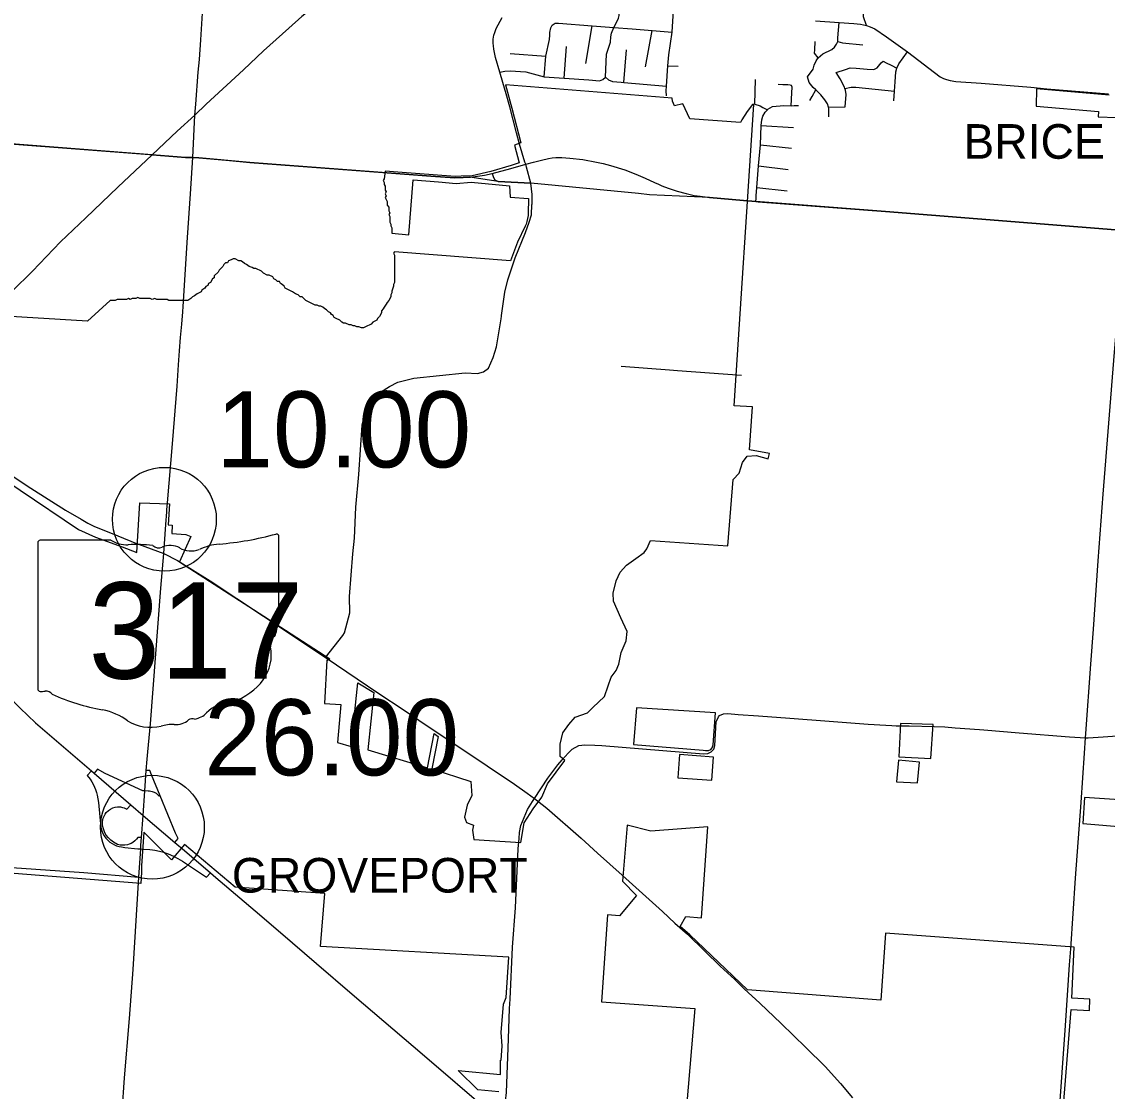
# Model space of a CAD drawing. Extents: x 1659811 to 1934326, y 644115 to 934867.
# Drawn here: x 1859259 to 1874937, y 684419 to 699875 of the extents above; entities that cross this region are included whole.
import ezdxf

# ---------------------------------------------------------------- set-up
doc = ezdxf.new("R2010")
doc.units = 0
for name, color, linetype in [('Default', 7, 'Continuous'), ('GM_X_City_Street', 7, 'Continuous'), ('GM_X_Corporation', 7, 'Continuous'), ('GM_X_Corporation_Text', 7, 'Continuous'), ('GM_X_County_Road', 7, 'Continuous'), ('GM_X_Interchange_Ramps', 7, 'Continuous'), ('GM_X_Interstate_Route', 7, 'Continuous'), ('GM_X_State_Route', 7, 'Continuous'), ('GM_X_State_Shield', 7, 'Continuous'), ('GM_X_Township', 7, 'Continuous'), ('GM_X_Township_Road', 7, 'Continuous'), ('GM_X_US_Route', 7, 'Continuous')]:
    doc.layers.add(name, color=color, linetype=linetype)

msp = doc.modelspace()

# ---------------------------------------------------------------- linework, layer by layer
at = {"layer": 'Default'}
for centre in [(1861320, 692685), (1861146, 688236)]:
    msp.add_circle(centre, 750, dxfattribs=at)
at = {"layer": 'GM_X_City_Street'}
for points in [[(1867689, 699074), (1867705, 699405), (1867764, 699580), (1867769, 699656), (1867777, 699710), (1867811, 699792), (1867859, 699882), (1867878, 699928), (1867890, 699967), (1867902, 700098), (1867921, 700440), (1867930, 700572), (1867936, 700755), (1867950, 700831), (1867977, 700904), (1867994, 700938), (1868035, 701005)], [(1871460, 699819), (1871415, 699946), (1871415, 700030), (1871420, 700173), (1871424, 700234)], [(1868572, 698806), (1868565, 698876), (1868570, 698945), (1868593, 699236), (1868606, 699398), (1868653, 699725), (1868674, 700037)], [(1866244, 698866), (1866239, 698881), (1866165, 699146), (1866104, 699357), (1866088, 699432), (1866078, 699480), (1866071, 699526), (1866067, 699566), (1866070, 699624), (1866080, 699680), (1866091, 699717), (1866100, 699747), (1866111, 699776), (1866198, 699935)], [(1870917, 698502), (1870917, 698622), (1870912, 698639), (1870897, 698688), (1870860, 698747), (1870799, 698819), (1870727, 698889), (1870690, 698925), (1870633, 698996), (1870607, 699079), (1870690, 699188), (1870705, 699246), (1870731, 699310), (1870762, 699355), (1870830, 699409), (1870960, 699473), (1871000, 699505), (1871028, 699550), (1871046, 699590), (1871048, 699643), (1871065, 699862)], [(1870722, 699888), (1871065, 699862), (1871277, 699848), (1871371, 699838), (1871460, 699819), (1871514, 699800), (1871580, 699770), (1871747, 699655), (1872052, 699438), (1872525, 699078), (1872570, 699053), (1872613, 699038), (1872668, 699024), (1872748, 699013), (1873117, 698986), (1873833, 698927), (1874063, 698907)], [(1866807, 699079), (1866829, 699375), (1866881, 699616), (1866885, 699683), (1866888, 699719), (1866899, 699787), (1866922, 699827)], [(1866922, 699827), (1866964, 699853), (1867010, 699856), (1867496, 699815), (1867561, 699811), (1867811, 699792), (1868074, 699771), (1868363, 699747), (1868653, 699725)], [(1867407, 699273), (1867496, 699815)], [(1868267, 699221), (1868363, 699747)], [(1870762, 699355), (1870711, 699419), (1870712, 699467), (1870719, 699588)], [(1871046, 699590), (1871114, 699571), (1871407, 699543)], [(1866312, 699417), (1866829, 699375)], [(1867092, 699059), (1867127, 699515)], [(1867957, 698996), (1867992, 699471)], [(1871853, 698732), (1871863, 698871), (1871873, 699006), (1871885, 699149), (1871899, 699206), (1871927, 699266), (1872052, 699438)], [(1868593, 699236), (1868740, 699231)], [(1871020, 699143), (1871158, 699184), (1871223, 699208), (1871311, 699203), (1871468, 699190), (1871564, 699185), (1871614, 699209), (1871672, 699281), (1871699, 699307), (1871745, 699283), (1871815, 699246), (1871899, 699206)], [(1866165, 699146), (1866236, 699163), (1866313, 699167), (1866542, 699151), (1866807, 699079), (1867092, 699059), (1867450, 699033), (1867606, 699022), (1867650, 699039), (1867689, 699074)], [(1871153, 698643), (1871165, 698825), (1871156, 698886), (1871148, 698910), (1871141, 698928), (1871078, 699051), (1871020, 699143)], [(1867689, 699074), (1867734, 699033), (1867793, 699010), (1867919, 699000), (1867957, 698996), (1868570, 698945)], [(1869845, 698682), (1869856, 699040)], [(1870371, 698662), (1870381, 698847), (1870385, 698931), (1870375, 698954), (1870357, 698960), (1870325, 698961), (1870253, 698962), (1870184, 698967)], [(1871148, 698910), (1871237, 698928), (1871307, 698927), (1871863, 698871)], [(1866550, 697772), (1866538, 697818), (1866524, 697845), (1866448, 698105), (1866404, 698269), (1866307, 698645), (1866244, 698866)], [(1870639, 698739), (1870674, 698795), (1870727, 698889)], [(1874063, 698907), (1874957, 698831)], [(1869845, 698682), (1869926, 698658), (1869965, 698637), (1870031, 698601)], [(1870031, 698601), (1870037, 698610), (1870102, 698650), (1870267, 698663), (1870371, 698662), (1870414, 698663), (1870480, 698666)], [(1870912, 698639), (1871153, 698643)], [(1869861, 697276), (1869864, 697323), (1869867, 697360), (1869878, 697481), (1869902, 697791), (1869931, 698097), (1869938, 698375), (1869948, 698457), (1869963, 698511), (1869998, 698568), (1870031, 698601)], [(1869938, 698375), (1870407, 698346)], [(1859028, 698117), (1861107, 697956)], [(1869931, 698097), (1870375, 698046)], [(1861107, 697956), (1861145, 697954), (1861625, 697914), (1861731, 697912)], [(1861731, 697912), (1861818, 697909), (1862259, 697869)], [(1862259, 697869), (1862555, 697842), (1864476, 697696)], [(1869902, 697791), (1870329, 697740)], [(1869878, 697481), (1870316, 697430)], [(1869895, 697274), (1871736, 697131), (1875175, 696856)], [(1874409, 686478), (1874480, 687499), (1874558, 688592), (1874608, 689305), (1874622, 689526), (1874627, 689590), (1874698, 690594), (1874737, 691097), (1874807, 692083), (1874880, 693048), (1875039, 695102), (1875078, 695560), (1875115, 696086), (1875158, 696658), (1875175, 696856)], [(1860916, 692337), (1860948, 692324), (1861312, 692190), (1861508, 692091), (1861979, 691797), (1862752, 691283), (1863647, 690689), (1863658, 690682)], [(1867063, 689207), (1867152, 689304), (1867211, 689363), (1867304, 689414), (1867394, 689426), (1867534, 689423), (1867637, 689418), (1869107, 689295), (1869168, 689300), (1869217, 689324), (1869253, 689365), (1869269, 689417), (1869291, 689760), (1869321, 689831), (1869337, 689848), (1869394, 689874), (1869457, 689877), (1869607, 689866), (1869898, 689844), (1870354, 689811), (1870919, 689768), (1871486, 689726), (1871740, 689708), (1871825, 689704), (1871887, 689701), (1871962, 689700)], [(1872437, 689689), (1872589, 689685), (1872741, 689673), (1873090, 689646), (1873156, 689641), (1873664, 689601), (1874391, 689543), (1874622, 689526), (1874647, 689526)], [(1874647, 689526), (1874663, 689526), (1874879, 689540), (1875079, 689554), (1875308, 689585), (1875466, 689617), (1875725, 689669), (1875775, 689677), (1875996, 689696), (1876147, 689675), (1876610, 689595), (1876828, 689561), (1877210, 689494), (1877360, 689471)], [(1866709, 688615), (1866844, 688509), (1867338, 688077), (1867575, 687860), (1867931, 687545), (1867936, 687540)], [(1866306, 685614), (1866312, 685751), (1866346, 686500), (1866391, 687069), (1866430, 687924), (1866442, 688073)], [(1858280, 687713), (1860155, 687580), (1860950, 687512)], [(1866232, 684150), (1866259, 684403), (1866289, 685179), (1866306, 685614)]]:
    msp.add_lwpolyline(points, dxfattribs=at)
at = {"layer": 'GM_X_Corporation'}
for points in [[(1857547, 694243), (1860080, 692538), (1860327, 692427), (1860710, 692289), (1860920, 692207), (1860963, 692923), (1861392, 692910), (1861373, 692607), (1861434, 692602), (1861427, 692478), (1861632, 692467), (1861702, 692436), (1861540, 692070), (1862757, 691285), (1863709, 690671), (1863676, 690644), (1863665, 690650), (1863632, 690025), (1863867, 690010), (1863822, 689460), (1864017, 689402), (1864114, 690321), (1864344, 690182), (1864258, 689355), (1865121, 689095), (1865214, 689588), (1865272, 689548), (1865183, 689079), (1865744, 688897), (1865760, 688694), (1865692, 688556), (1865656, 688381), (1865683, 688304), (1865782, 688264), (1865771, 688194), (1865790, 688059), (1866466, 688014), (1866514, 688300), (1866645, 688503), (1866769, 688671), (1866852, 688861), (1867103, 689199), (1867038, 689259), (1867038, 689436), (1867076, 689597), (1867160, 689719), (1867254, 689824), (1867432, 689887), (1867506, 689964), (1867676, 690125), (1867728, 690280), (1867771, 690404), (1867843, 690501), (1867883, 690594), (1867915, 690759), (1867991, 690927), (1868002, 691062), (1867911, 691263), (1867807, 691503), (1867799, 691618), (1867843, 691794), (1867903, 691921), (1867995, 692022), (1868130, 692119), (1868250, 692205), (1868289, 692258), (1868340, 692380), (1869458, 692303), (1869536, 693259), (1869622, 693353), (1869670, 693504), (1869736, 693599), (1869866, 693609), (1870041, 693559), (1870059, 693637), (1869771, 693687), (1869812, 694308), (1869550, 694325), (1869833, 698679), (1869814, 698680), (1869737, 698577), (1869660, 698456), (1869641, 698418), (1868907, 698473), (1868806, 698690), (1868687, 698662), (1868657, 698726), (1868651, 698772), (1866245, 698962), (1866336, 698628), (1866470, 698123), (1866374, 698093), (1866443, 697834), (1866328, 697798), (1866034, 697709), (1865767, 697650), (1865608, 697641), (1865518, 697637), (1864693, 697702), (1864510, 697716), (1864495, 697606), (1864481, 697579), (1864495, 697551), (1864495, 697524), (1864508, 697497), (1864508, 697469), (1864508, 697442), (1864522, 697415), (1864508, 697388), (1864522, 697360), (1864508, 697333), (1864536, 697279), (1864536, 697224), (1864563, 697197), (1864563, 697142), (1864576, 697115), (1864563, 697088), (1864576, 697060), (1864576, 696979), (1864590, 696951), (1864590, 696924), (1864604, 696897), (1864604, 696818), (1864851, 696794), (1864914, 697591), (1865278, 697562), (1865532, 697538), (1865750, 697559), (1866305, 697505), (1866315, 697341), (1866579, 697320), (1866574, 697105), (1866572, 697073), (1866566, 697034), (1866555, 696987), (1866543, 696952), (1866530, 696922), (1866419, 696689), (1866317, 696418), (1864641, 696550), (1864631, 696529), (1864645, 696501), (1864645, 696229), (1864645, 696106), (1864631, 696079), (1864631, 696052), (1864617, 696024), (1864604, 695983), (1864604, 695956), (1864590, 695929), (1864590, 695902), (1864563, 695847), (1864536, 695820), (1864522, 695793), (1864495, 695752), (1864481, 695724), (1864454, 695697), (1864454, 695670), (1864426, 695615), (1864399, 695588), (1864386, 695561), (1864331, 695533), (1864304, 695506), (1864222, 695465), (1864195, 695452), (1864167, 695452), (1864127, 695465), (1864099, 695465), (1864072, 695479), (1864045, 695479), (1864017, 695493), (1863990, 695493), (1863936, 695520), (1863908, 695520), (1863881, 695533), (1863854, 695561), (1863799, 695588), (1863772, 695602), (1863758, 695629), (1863731, 695643), (1863718, 695670), (1863690, 695683), (1863663, 695711), (1863636, 695724), (1863608, 695752), (1863581, 695765), (1863554, 695765), (1863527, 695779), (1863499, 695779), (1863390, 695833), (1863363, 695847), (1863309, 695902), (1863281, 695902), (1863254, 695929), (1863213, 695942), (1863172, 695970), (1863063, 696024), (1863049, 696052), (1863022, 696079), (1862995, 696092), (1862981, 696120), (1862954, 696120), (1862927, 696147), (1862899, 696161), (1862886, 696188), (1862831, 696215), (1862804, 696215), (1862750, 696242), (1862722, 696270), (1862640, 696311), (1862613, 696311), (1862586, 696324), (1862545, 696338), (1862504, 696365), (1862477, 696379), (1862450, 696406), (1862422, 696420), (1862395, 696420), (1862341, 696447), (1862313, 696447), (1862286, 696433), (1862245, 696420), (1862231, 696392), (1862204, 696392), (1862177, 696365), (1862163, 696338), (1862109, 696283), (1862095, 696256), (1862041, 696201), (1862041, 696174), (1862013, 696161), (1861986, 696106), (1861959, 696092), (1861945, 696065), (1861918, 696051), (1861904, 696024), (1861863, 695997), (1861850, 695970), (1861795, 695942), (1861754, 695915), (1861727, 695902), (1861700, 695874), (1861659, 695847), (1861427, 695847), (1861386, 695847), (1861359, 695861), (1861209, 695861), (1861182, 695874), (1861141, 695861), (1861113, 695874), (1860964, 695874), (1860936, 695888), (1860909, 695874), (1860854, 695874), (1860827, 695861), (1860800, 695874), (1860773, 695861), (1860636, 695861), (1860609, 695847), (1860536, 695847), (1860208, 695548), (1858861, 695628)], [(1874965, 698815), (1873913, 698904), (1873911, 698654), (1874808, 698580), (1874806, 698501), (1875072, 698489)], [(1874157, 682347), (1874416, 685600), (1874679, 685587), (1874687, 685752), (1874424, 685765), (1874461, 686501), (1871735, 686705), (1871665, 685737), (1869741, 685884), (1868909, 686681), (1868771, 686799), (1868852, 686943), (1869076, 686927), (1869167, 688241), (1868345, 688180), (1868005, 688265), (1867936, 687454), (1868139, 687250), (1867891, 686955), (1867717, 686969), (1867633, 685710), (1868979, 685617), (1868858, 684195)], [(1866150, 684410), (1865849, 684442), (1865565, 684718), (1866173, 684662), (1866174, 684871), (1866184, 684870), (1866199, 685075), (1866182, 685269), (1866216, 685678), (1866258, 685776), (1866295, 686357), (1863575, 686513), (1863635, 687276), (1862344, 687368), (1861611, 687984), (1861425, 687763), (1861021, 688163), (1860987, 687679), (1860987, 687588), (1860981, 687422), (1858232, 687641), (1858240, 687741), (1856501, 687880), (1856343, 684081)]]:
    msp.add_lwpolyline(points, dxfattribs=at)
for points in [[(1868140, 689960), (1868096, 689429), (1869099, 689347), (1869133, 689343), (1869176, 689343), (1869210, 689358), (1869232, 689382), (1869245, 689427), (1869277, 689888)], [(1871926, 689253), (1872387, 689229), (1872422, 689719), (1871952, 689736)], [(1868757, 689286), (1868737, 688951), (1869226, 688915), (1869250, 689249)], [(1871924, 689203), (1871892, 688889), (1872196, 688876), (1872227, 689175)], [(1874584, 688288), (1875904, 688180), (1875799, 686401), (1877038, 686309), (1877141, 687752), (1877160, 687756), (1877207, 688277), (1877191, 688281), (1877206, 688492), (1874607, 688664)]]:
    msp.add_lwpolyline(points, close=True, dxfattribs=at)
at = {"layer": 'GM_X_County_Road'}
for points in [[(1866538, 697818), (1866649, 697848), (1866766, 697876), (1866866, 697900), (1866920, 697909), (1866973, 697914), (1867058, 697913), (1867177, 697905), (1867362, 697883), (1867559, 697847), (1867659, 697824), (1867763, 697798), (1867969, 697733), (1868127, 697672), (1868265, 697613), (1868398, 697552), (1868456, 697526), (1868503, 697506), (1868595, 697469), (1868727, 697427), (1868853, 697394), (1868971, 697366), (1869057, 697354), (1869162, 697341)], [(1864476, 697696), (1865166, 697644), (1865514, 697621), (1865633, 697623), (1865732, 697627), (1865743, 697629)], [(1865743, 697629), (1865841, 697641), (1865943, 697657), (1866056, 697684), (1866321, 697756), (1866538, 697818)], [(1866610, 697540), (1866550, 697772)], [(1866628, 697235), (1866629, 697236), (1866630, 697380), (1866610, 697540)], [(1866188, 695618), (1866190, 695628), (1866235, 695967), (1866282, 696143), (1866385, 696462), (1866535, 696827), (1866587, 696977), (1866621, 697084), (1866628, 697235)], [(1869162, 697341), (1869190, 697337), (1869683, 697291), (1869861, 697276), (1869895, 697274)], [(1853309, 697139), (1853349, 697097), (1853405, 697056), (1854433, 696395), (1856032, 695346), (1856581, 694984), (1856820, 694829), (1857143, 694619), (1857252, 694544), (1857686, 694254), (1857735, 694222), (1858576, 693668), (1859390, 693133), (1859891, 692817), (1860116, 692685), (1860212, 692629), (1860303, 692586), (1860649, 692444), (1860916, 692337)], [(1863647, 690689), (1863896, 691006), (1863919, 691045), (1863941, 691117), (1863997, 691334), (1863994, 691569), (1864043, 692185), (1864064, 692410), (1864085, 692862), (1864126, 693333), (1864175, 694045), (1864241, 694305), (1864273, 694340), (1864297, 694374), (1864332, 694409), (1864441, 694522), (1864570, 694605), (1864693, 694666), (1864923, 694722), (1865662, 694803), (1865844, 694792), (1865929, 694818), (1866002, 694868), (1866070, 695025), (1866092, 695101), (1866114, 695176), (1866182, 695583), (1866188, 695618)], [(1863658, 690682), (1864403, 690179), (1864782, 689927), (1864994, 689782), (1865287, 689585), (1865588, 689386), (1866376, 688859), (1866561, 688728), (1866664, 688651), (1866709, 688615)], [(1871962, 689700), (1872074, 689699), (1872437, 689689)], [(1866664, 688651), (1866859, 688946), (1867002, 689139), (1867063, 689207)], [(1866442, 688073), (1866449, 688157), (1866468, 688261), (1866562, 688492), (1866635, 688609), (1866664, 688651)], [(1867936, 687540), (1868515, 687016), (1868692, 686848), (1868877, 686688), (1869123, 686443), (1869346, 686229), (1869556, 686034), (1869695, 685902), (1869918, 685691), (1870225, 685397), (1870585, 685050), (1870861, 684777), (1871083, 684532), (1871258, 684324)], [(1874049, 681380), (1874122, 682361), (1874149, 682757), (1874214, 683655), (1874258, 684283), (1874286, 684692), (1874332, 685369), (1874393, 686246), (1874409, 686478)]]:
    msp.add_lwpolyline(points, dxfattribs=at)
at = {"layer": 'GM_X_Interchange_Ramps'}
for points in [[(1860265, 689050), (1860207, 688985), (1860247, 688929), (1860271, 688891), (1860294, 688849), (1860310, 688815), (1860324, 688779), (1860338, 688738), (1860349, 688699), (1860360, 688646), (1860366, 688593), (1860404, 688229), (1860417, 688181), (1860432, 688145), (1860450, 688113), (1860475, 688077), (1860507, 688042), (1860533, 688020), (1860565, 687998), (1860598, 687980), (1860627, 687968), (1860665, 687957), (1860700, 687951), (1860747, 687943), (1860938, 687925), (1860978, 687922)], [(1861038, 688759), (1861010, 688760), (1860467, 689011), (1860355, 689074), (1860305, 689015)], [(1861471, 688017), (1861520, 688071), (1861478, 688150), (1861257, 688688), (1861132, 688992), (1861109, 689054), (1861058, 689057)], [(1861257, 688688), (1861245, 688683), (1861226, 688703), (1861204, 688721), (1861179, 688735), (1861150, 688747), (1861124, 688753), (1861105, 688755), (1861086, 688756), (1861038, 688759)], [(1860991, 688085), (1860937, 688089), (1860918, 688063), (1860893, 688037), (1860866, 688016), (1860838, 688000), (1860812, 687989), (1860786, 687981), (1860750, 687975), (1860715, 687974), (1860681, 687978), (1860644, 687988), (1860585, 688020), (1860545, 688048), (1860511, 688080), (1860480, 688120), (1860461, 688153), (1860448, 688184), (1860435, 688227), (1860428, 688271), (1860428, 688317), (1860437, 688366), (1860449, 688396), (1860463, 688423), (1860481, 688447), (1860511, 688477), (1860541, 688498), (1860577, 688515), (1860611, 688525), (1860645, 688529), (1860684, 688528), (1860715, 688522), (1860741, 688514), (1860776, 688498), (1860836, 688560)], [(1860978, 687922), (1861013, 687919), (1861112, 687912), (1861146, 687909), (1861184, 687903), (1861291, 687879), (1861374, 687852), (1861450, 687818), (1861516, 687784), (1861583, 687744), (1861930, 687513), (1861985, 687576)]]:
    msp.add_lwpolyline(points, dxfattribs=at)
at = {"layer": 'GM_X_Interstate_Route'}
for points in [[(1866661, 702405), (1866135, 702037), (1865754, 701771), (1863948, 700473), (1863307, 699951), (1863118, 699783), (1862753, 699455), (1862463, 699181), (1861921, 698685), (1861760, 698527)], [(1861760, 698527), (1861505, 698295), (1861145, 697954)], [(1861145, 697954), (1860646, 697483), (1860184, 697039), (1859820, 696695), (1859416, 696269), (1859123, 695983), (1858883, 695722), (1858802, 695627)]]:
    msp.add_lwpolyline(points, dxfattribs=at)
at = {"layer": 'GM_X_State_Route'}
for points in [[(1861845, 699612), (1861845, 699613), (1861872, 699998), (1861899, 700386), (1861900, 700388)], [(1861810, 699147), (1861810, 699148), (1861825, 699330), (1861845, 699612)], [(1861773, 698682), (1861773, 698682), (1861810, 699147)], [(1861731, 697912), (1861760, 698527), (1861773, 698682)], [(1861697, 697387), (1861731, 697912)], [(1861656, 696756), (1861697, 697387)], [(1861591, 695758), (1861656, 696756)], [(1861366, 692925), (1861438, 693776), (1861504, 694611), (1861524, 694917), (1861540, 695118), (1861554, 695313), (1861570, 695504), (1861586, 695685), (1861591, 695758)], [(1861342, 692610), (1861355, 692792), (1861357, 692820)], [(1861357, 692820), (1861366, 692925)], [(1861082, 689327), (1861118, 689728), (1861270, 691692), (1861312, 692190), (1861342, 692610)], [(1861015, 688403), (1861038, 688759), (1861058, 689057), (1861072, 689219)], [(1861072, 689219), (1861082, 689327)], [(1860982, 687976), (1860991, 688085), (1861015, 688403)], [(1860950, 687512), (1860978, 687922), (1860982, 687976)], [(1860712, 684123), (1860745, 684612), (1860816, 685471), (1860868, 686179), (1860950, 687512)]]:
    msp.add_lwpolyline(points, dxfattribs=at)
at = {"layer": 'GM_X_State_Shield'}
for p, q in [((1859493, 692347), (1859493, 690234)), ((1860547, 692384), (1859528, 692384)), ((1862974, 691331), (1862974, 692436)), ((1862973, 691331), (1862974, 691331))]:
    msp.add_line(p, q, dxfattribs=at)
for centre, major_axis, start_param, end_param in [((1859533, 692352), (40.3, 0), 1.712693, 3.28349), ((1860790, 692629), (391, 0), 4.042523, 4.731795), ((1861734, 695265), (3691, 0), 4.814394, 5.042369), ((1862935, 692441), (38.7, 0), 6.141152, 7.989035), ((1860919, 691197), (1404, 0), 1.404758, 1.657858), ((1861238, 692363), (113, 0), 3.836095, 5.185415), ((1861404, 692119), (235, 0), 0.950623, 2.079405), ((1861706, 692454), (282, 0), 4.081561, 5.145723), ((1862205, 691738), (743, 0), 1.699011, 2.107814), ((1862965, 691250), (60, 0), 1.883978, 3.671073), ((1862932, 691326), (41.5, 0), 5.05454, 6.418171), ((1862583, 691110), (360, 0), 5.934695, 6.695948), ((1863113, 690868), (262, 0), 2.387724, 3.262537), ((1861941, 690727), (923, 0), 5.101752, 6.440018), ((1859534, 690230), (40.7, 0), 3.00124, 4.508301), ((1859540, 690446), (310, 0), 4.665946, 4.897461), ((1859603, 690112), (112, 0), 0.519207, 1.627899), ((1861017, 692011), (2665, 0), 4.195997, 4.488961), ((1862330, 689641), (506, 0), 1.647645, 2.488434), ((1860222, 689285), (834, 0), 0.823519, 1.323587), ((1861689, 690029), (298, 0), 4.937069, 5.64225), ((1861124, 690102), (529, 0), 4.026481, 4.996735), ((1861430, 689371), (435, 0), 1.495662, 1.94098), ((1861468, 689943), (282, 0), 4.691044, 5.507374), ((1861723, 689739), (79.4, 0), 1.147584, 2.315152)]:
    msp.add_ellipse(centre, major_axis=major_axis, ratio=0.8, start_param=start_param, end_param=end_param, dxfattribs=at)
at = {"layer": 'GM_X_Township'}
msp.add_lwpolyline([(1875175, 696856), (1871736, 697131), (1869861, 697276), (1869683, 697291), (1869190, 697337), (1868327, 697375), (1868165, 697391), (1866610, 697540), (1866139, 697568), (1865732, 697627), (1865633, 697623), (1865514, 697621), (1865166, 697644), (1862555, 697842), (1861818, 697909), (1861731, 697912), (1861625, 697914), (1861145, 697954), (1857989, 698197)], dxfattribs=at)
at = {"layer": 'GM_X_Township_Road'}
for points in [[(1866056, 697684), (1866071, 697623), (1866094, 697589), (1866139, 697568), (1866610, 697540)], [(1867918, 694897), (1868614, 694845), (1868731, 694836), (1868731, 694836)], [(1868731, 694836), (1869653, 694767)]]:
    msp.add_lwpolyline(points, dxfattribs=at)
at = {"layer": 'GM_X_US_Route'}
for points in [[(1856652, 693074), (1856737, 693020), (1856777, 692989), (1856897, 692893), (1857063, 692753), (1857202, 692621), (1857327, 692490), (1857455, 692349), (1857598, 692163), (1857712, 692012), (1858010, 691573), (1858344, 691078), (1858661, 690619), (1858855, 690377), (1859060, 690138), (1859236, 689954), (1859458, 689742), (1860265, 689050), (1860305, 689015), (1860836, 688560), (1861015, 688403)], [(1861015, 688403), (1861471, 688017), (1861608, 687899)], [(1861608, 687899), (1861985, 687576), (1862065, 687507)], [(1862065, 687507), (1862694, 686973), (1863169, 686564), (1863517, 686267)], [(1863517, 686267), (1864034, 685824), (1865077, 684934), (1865996, 684144), (1866100, 684050), (1866211, 683955), (1866765, 683491), (1867122, 683185), (1867715, 682659), (1867973, 682400), (1868205, 682168), (1868727, 681617), (1869171, 681145), (1869529, 680799), (1869787, 680588), (1869991, 680435), (1870216, 680279), (1870485, 680114), (1872095, 679234), (1873802, 678296), (1873853, 678268)]]:
    msp.add_lwpolyline(points, dxfattribs=at)

# ---------------------------------------------------------------- texts
at = {"layer": 'Default'}
for s, p in [('10.00', (1862070, 693435)), ('26.00', (1861896, 688985))]:
    msp.add_text(s, height=1100, dxfattribs=at).set_placement(p)
at = {"layer": 'GM_X_Corporation_Text'}
for s, p in [('BRICE', (1872859, 697895)), ('GROVEPORT', (1862294, 687291))]:
    msp.add_text(s, height=500, rotation=0, dxfattribs=at).set_placement(p)
at = {"layer": 'GM_X_State_Shield'}
msp.add_text('317', height=1392.2, dxfattribs=at).set_placement((1860223, 690383))

doc.saveas('drawing.dxf')
